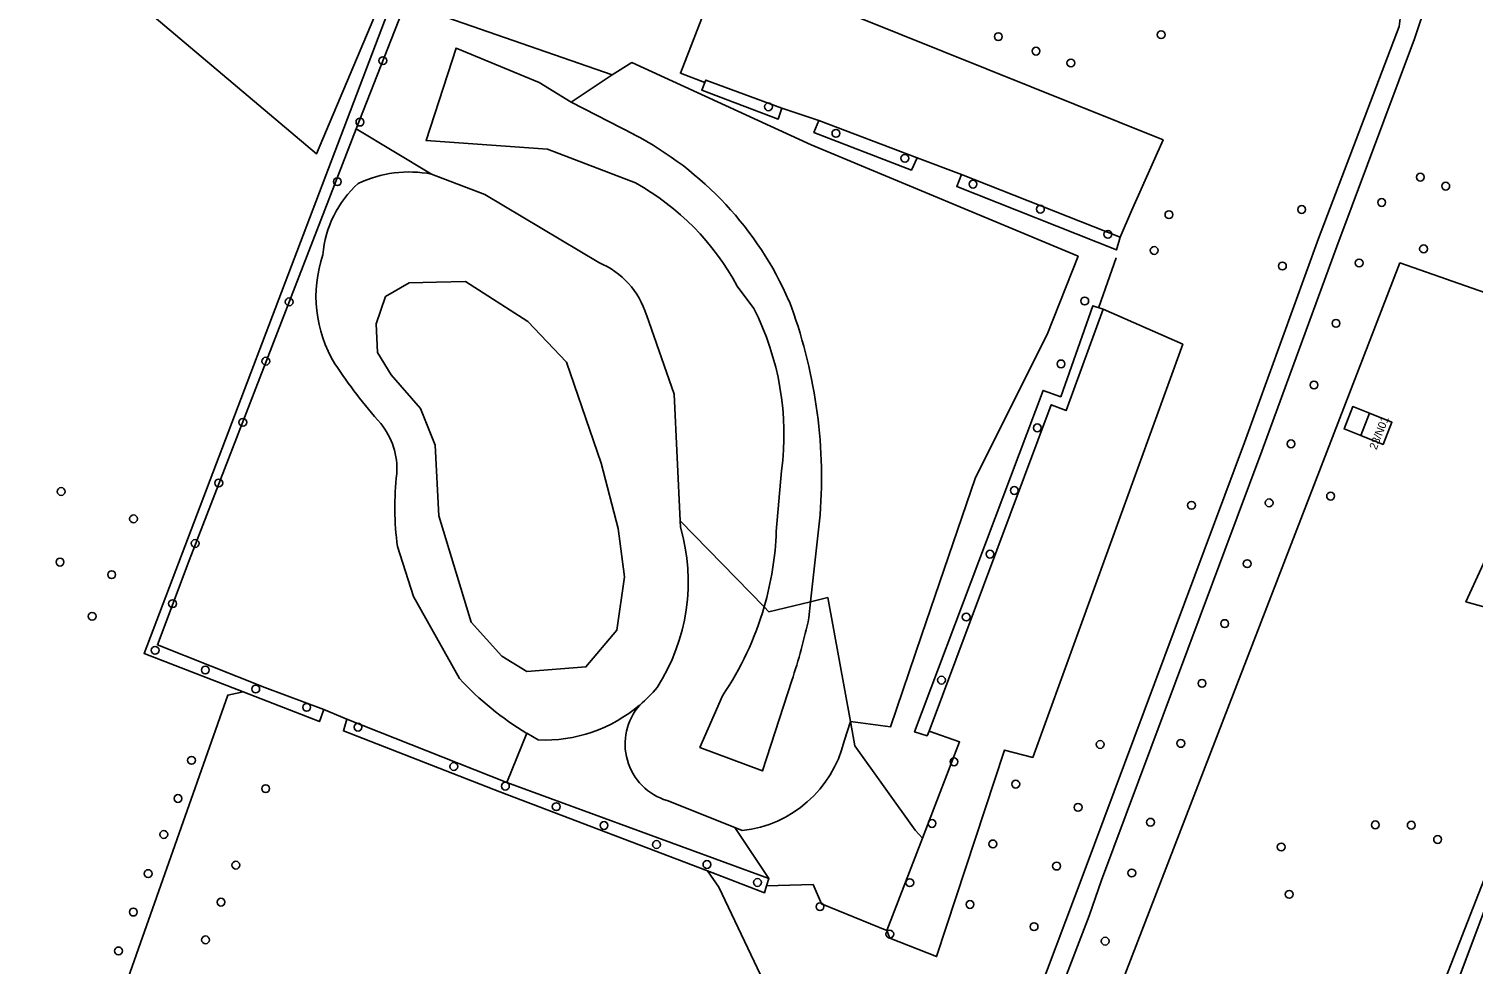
# Model space of a CAD drawing. Extents: x 155209 to 156748, y 385356 to 388487.
# Drawn here: x 155473 to 155653.4, y 386622.5 to 386739.4 of the extents above; entities that cross this region are included whole.
import ezdxf

# ---------------------------------------------------------------- set-up
doc = ezdxf.new("R2010")
doc.units = 0
for name, color, linetype in [('IMGEO_Boom', 7, 'Continuous'), ('IMGEO_Erf', 7, 'Continuous'), ('IMGEO_Gemengd_bos', 7, 'Continuous'), ('IMGEO_Groenvoorziening', 7, 'Continuous'), ('IMGEO_Haag', 7, 'Continuous'), ('IMGEO_Hek', 7, 'Continuous'), ('IMGEO_Loofbos', 7, 'Continuous'), ('IMGEO_Meer_plas_ven_vijver', 7, 'Continuous'), ('IMGEO_Oever', 7, 'Continuous'), ('IMGEO_Pand', 7, 'Continuous'), ('IMGEO_Pand_nummerreeks', 7, 'Continuous'), ('IMGEO_Rijbaan_lokaal_halfverhard', 7, 'Continuous')]:
    doc.layers.add(name, color=color, linetype=linetype)

msp = doc.modelspace()

# ---------------------------------------------------------------- linework, layer by layer
at = {"layer": 'IMGEO_Boom'}
for centre in [(155594.11, 386738.47), (155614.46, 386738.72), (155517.21, 386735.47), (155598.82, 386736.66), (155603.18, 386735.18), (155565.39, 386729.7), (155514.34, 386727.79), (155573.82, 386726.38), (155582.43, 386723.26), (155646.85, 386720.9), (155511.51, 386720.34), (155590.95, 386720.03), (155650.02, 386719.78), (155642.02, 386717.74), (155599.37, 386716.9), (155615.43, 386716.21), (155632.02, 386716.86), (155607.8, 386713.76), (155613.59, 386711.74), (155647.25, 386711.94), (155639.2, 386710.17), (155629.61, 386709.79), (155505.5, 386705.31), (155604.91, 386705.41), (155636.31, 386702.62), (155502.58, 386697.89), (155601.95, 386697.55), (155633.55, 386694.91), (155499.71, 386690.24), (155598.98, 386689.56), (155630.68, 386687.56), (155477.01, 386681.59), (155496.7, 386682.66), (155596.11, 386681.73), (155635.63, 386681.02), (155618.25, 386679.87), (155627.95, 386680.18), (155486.05, 386678.18), (155493.75, 386675.1), (155593.07, 386673.77), (155476.86, 386672.77), (155625.21, 386672.57), (155483.32, 386671.2), (155490.93, 386667.58), (155480.88, 386665.99), (155590.1, 386665.9), (155622.39, 386665.08), (155488.75, 386661.74), (155495.02, 386659.27), (155587.01, 386658.01), (155619.57, 386657.61), (155501.32, 386656.9), (155507.68, 386654.61), (155514.1, 386652.13), (155606.84, 386649.97), (155616.91, 386650.1), (155493.3, 386647.99), (155526.07, 386647.21), (155588.58, 386647.8), (155596.29, 386645.01), (155491.6, 386643.21), (155502.56, 386644.44), (155532.52, 386644.75), (155538.87, 386642.19), (155604.08, 386642.1), (155544.84, 386639.84), (155585.83, 386640.09), (155613.12, 386640.24), (155641.22, 386639.91), (155645.71, 386639.87), (155489.83, 386638.71), (155649, 386638.09), (155551.4, 386637.45), (155593.43, 386637.53), (155629.46, 386637.15), (155498.84, 386634.88), (155557.7, 386634.96), (155601.39, 386634.76), (155487.88, 386633.82), (155564.02, 386632.71), (155583.05, 386632.68), (155610.79, 386633.9), (155630.46, 386631.22), (155486.02, 386629.01), (155496.98, 386630.25), (155571.83, 386629.68), (155590.57, 386629.96), (155598.58, 386627.18), (155495.05, 386625.53), (155580.55, 386626.25), (155607.46, 386625.37), (155484.17, 386624.15)]:
    msp.add_circle(centre, 0.489, dxfattribs=at)
at = {"layer": 'IMGEO_Erf'}
msp.add_lwpolyline([(155640.49, 386691.38), (155638.4, 386692.22), (155637.32, 386689.42), (155639.41, 386688.59)], close=True, dxfattribs=at)
at = {"layer": 'IMGEO_Gemengd_bos'}
for points in [[(155429, 386766.39), (155442.17, 386765.25), (155453.97, 386761.78), (155456.24, 386773.38), (155448.12, 386779.05), (155437.51, 386783.89), (155451.92, 386808.13), (155477.38, 386797.93), (155505.35, 386780.3), (155502.98, 386770.15), (155524.05, 386759.67), (155508.92, 386723.82), (155488.64, 386740.97), (155469.58, 386744.62)], [(155554.38, 386733.89), (155559.71, 386747.69), (155614.71, 386725.57), (155610.76, 386716.71), (155609.34, 386713.39), (155608.88, 386711.8), (155588.92, 386719.73), (155589.49, 386721.25), (155583.96, 386723.33), (155583.26, 386721.79), (155571.06, 386726.49), (155571.68, 386727.98), (155567.07, 386729.53), (155566.62, 386728.16), (155557.06, 386731.77), (155557.42, 386732.74)], [(155557.42, 386732.74), (155557.06, 386731.77), (155566.62, 386728.16), (155567.07, 386729.53), (155557.55, 386733.04)], [(155571.68, 386727.98), (155571.06, 386726.49), (155583.26, 386721.79), (155583.96, 386723.33)], [(155589.49, 386721.25), (155588.92, 386719.73), (155608.88, 386711.8), (155609.34, 386713.39)], [(155607.21, 386704.4), (155605.92, 386704.82), (155601.92, 386693.45), (155599.71, 386694.23), (155583.65, 386651.53), (155585.21, 386651.06), (155585.46, 386651.62), (155600.73, 386692.44), (155602.58, 386691.71)]]:
    msp.add_lwpolyline(points, close=True, dxfattribs=at)
for points in [[(155634.14, 386713.25), (155644.18, 386739.73), (155644.34, 386740.74), (155643.64, 386741.11), (155602.96, 386756.31), (155548.13, 386775.92), (155545.77, 386776.43)], [(155485.14, 386620.07), (155497.83, 386656.14), (155499.74, 386656.54), (155487.37, 386661.36), (155524.86, 386760.1)], [(155520.05, 386742.67), (155545.88, 386733.7), (155548.3, 386735.23), (155570.71, 386724.93), (155604.08, 386711.01), (155600.2, 386701.22), (155591.24, 386683.36), (155584.5, 386663.6), (155580.62, 386652.16), (155575.62, 386652.84), (155576.18, 386649.81), (155583.73, 386639.23), (155584.63, 386638.24), (155589.27, 386650.29), (155585.46, 386651.62), (155585.21, 386651.06), (155583.65, 386651.53), (155599.71, 386694.23), (155601.92, 386693.45), (155605.92, 386704.82), (155607.21, 386704.4), (155617.16, 386700), (155598.42, 386648.34), (155594.89, 386649.26), (155586.4, 386623.44), (155580.55, 386625.76), (155580.19, 386626.71), (155572.02, 386630.03), (155570.97, 386632.44), (155565.14, 386632.28), (155564.88, 386631.43), (155557.77, 386634.17), (155559.17, 386632.13), (155564.4, 386621.18)], [(155600.2, 386701.22), (155604.08, 386711.01), (155570.71, 386724.93), (155548.3, 386735.23), (155545.88, 386733.7), (155540.72, 386730.27), (155548.59, 386726.23)], [(155584.86, 386581.8), (155593.26, 386603.28), (155604.83, 386634.04), (155624.86, 386687.72), (155634.14, 386713.25)], [(155571.83, 386678.68), (155570.65, 386667.82), (155572.79, 386668.33), (155575.62, 386652.84), (155580.62, 386652.16), (155584.5, 386663.6), (155591.24, 386683.36), (155600.2, 386701.22)]]:
    msp.add_lwpolyline(points, dxfattribs=at)
for centre, radius, start, end in [((155528.8, 386688.4), 42.7, 23.5165, 62.3943), ((155509.69, 386683.33), 62.32, 355.7271, 20.7754)]:
    msp.add_arc(centre, radius, start, end, dxfattribs=at)
at = {"layer": 'IMGEO_Groenvoorziening'}
for points in [[(155524.05, 386759.67), (155502.98, 386770.15), (155488.64, 386740.97), (155508.92, 386723.82)], [(155489.03, 386662.42), (155492.99, 386672.97), (155513.88, 386726.96), (155520.05, 386742.67), (155526.72, 386759.39), (155524.86, 386760.1), (155487.37, 386661.36), (155499.74, 386656.54), (155509.27, 386652.83), (155509.85, 386654.32), (155502.46, 386657.1)], [(155559.71, 386747.69), (155554.38, 386733.89), (155557.42, 386732.74), (155557.55, 386733.04), (155567.07, 386729.53), (155571.68, 386727.98), (155583.96, 386723.33), (155589.49, 386721.25), (155609.34, 386713.39), (155610.76, 386716.71), (155614.71, 386725.57)], [(155609.41, 386594.06), (155600.79, 386597.51), (155644.3, 386710.17), (155668.19, 386701.83), (155652.54, 386667.82), (155666.82, 386663.83), (155639.02, 386592.67), (155625.52, 386597.7), (155615.16, 386569.9), (155603.8, 386572.97), (155603.06, 386575.78), (155593.6, 386579.74), (155598.69, 386593.98), (155608.22, 386590.58)], [(155617.16, 386700), (155607.21, 386704.4), (155602.58, 386691.71), (155600.73, 386692.44), (155585.46, 386651.62), (155589.27, 386650.29), (155584.63, 386638.24), (155580.19, 386626.71), (155580.55, 386625.76), (155586.4, 386623.44), (155594.89, 386649.26), (155598.42, 386648.34)], [(155559.17, 386632.13), (155557.77, 386634.17), (155531.83, 386644.04), (155512.27, 386651.66), (155512.7, 386653.15), (155509.85, 386654.32), (155509.27, 386652.83), (155499.74, 386656.54), (155497.83, 386656.14), (155485.14, 386620.07), (155519.77, 386606.37), (155574.54, 386583.62), (155584.21, 386612.25), (155564.4, 386621.18)], [(155532.68, 386645.23), (155512.7, 386653.15), (155512.27, 386651.66), (155531.83, 386644.04), (155557.77, 386634.17), (155564.88, 386631.43), (155565.14, 386632.28), (155565.45, 386633.21)]]:
    msp.add_lwpolyline(points, close=True, dxfattribs=at)
for points in [[(155687.33, 386713.23), (155695.66, 386734.59), (155661.19, 386747.92), (155654.58, 386750.61), (155650.78, 386752.11), (155646.13, 386738.19), (155636.4, 386712.24), (155627.03, 386686.65), (155606.99, 386633), (155605.46, 386628.53), (155594.88, 386600.99), (155587.3, 386580.96)], [(155523.27, 386721.29), (155513.88, 386726.96), (155492.99, 386672.97), (155489.03, 386662.42), (155502.46, 386657.1), (155509.85, 386654.32), (155512.7, 386653.15), (155532.68, 386645.23), (155535.18, 386651.36)], [(155564.85, 386667.17), (155554.36, 386677.91), (155554.4, 386677.12)], [(155526.79, 386658.21), (155521.02, 386668.47), (155519.02, 386674.72)], [(155570.43, 386665.81), (155570.65, 386667.82), (155565.43, 386666.57), (155564.85, 386667.17)], [(155574.84, 386650.36), (155575.62, 386652.84), (155572.79, 386668.33), (155570.65, 386667.82), (155570.43, 386665.81)], [(155559.66, 386656.05), (155556.83, 386649.59), (155564.65, 386646.65), (155568.3, 386657.96)], [(155568.3, 386657.96), (155564.65, 386646.65), (155556.83, 386649.59), (155559.66, 386656.05)], [(155576.18, 386649.81), (155575.62, 386652.84), (155574.84, 386650.36)], [(155536.61, 386650.53), (155535.18, 386651.36), (155532.68, 386645.23), (155565.45, 386633.21), (155561.2, 386639.58), (155552.72, 386642.95)], [(155562.12, 386639.22), (155561.2, 386639.58), (155565.45, 386633.21), (155565.14, 386632.28), (155570.97, 386632.44), (155572.02, 386630.03), (155580.19, 386626.71), (155584.63, 386638.24), (155583.73, 386639.23), (155576.18, 386649.81)], [(155723.96, 386623.91), (155723.78, 386623.66), (155661.74, 386647.58), (155649.36, 386614.6), (155654.71, 386612.58), (155718.88, 386588.39)], [(155649.36, 386614.6), (155661.74, 386647.58)], [(155552.72, 386642.95), (155561.2, 386639.58), (155562.12, 386639.22)]]:
    msp.add_lwpolyline(points, dxfattribs=at)
for centre, radius, start, end in [((155520.48, 386706.9), 14.65, 79.0403, 115.6529), ((155523.05, 386710.15), 13.37, 131.7858, 175.4859), ((155525.02, 386705.97), 16.17, 161.1281, 211.2567), ((155567.03, 386734.46), 66.91, 213.4524, 221.5404), ((155510.03, 386684.44), 8.93, 356.0961, 39.2171), ((155556.42, 386679.63), 37.72, 173.6046, 187.4889), ((155530.83, 386670.33), 24.53, 327.3618, 16.0656), ((155526.9, 386678.13), 39.5, 326.0222, 343.8961), ((155526.9, 386678.13), 39.5, 326.0222, 343.8961), ((155498.28, 386681.19), 73.78, 341.6442, 347.9678), ((155498.28, 386681.19), 73.78, 341.6442, 347.9678), ((155555.47, 386684.79), 39.11, 222.8249, 238.7488), ((155537.49, 386668.8), 18.24, 310.3425, 320.1013), ((155537.4, 386668.87), 18.35, 267.5225, 310.4059), ((155554.85, 386650.02), 7.38, 138.6882, 253.2457), ((155554.85, 386650.02), 7.38, 138.6882, 253.2457), ((155560.57, 386653.82), 14.68, 276.0714, 346.3954), ((155560.57, 386653.82), 14.68, 276.0714, 346.3954)]:
    msp.add_arc(centre, radius, start, end, dxfattribs=at)
at = {"layer": 'IMGEO_Haag'}
for points in [[(155520.05, 386742.67), (155526.72, 386759.39), (155524.86, 386760.1), (155487.37, 386661.36), (155499.74, 386656.54), (155509.27, 386652.83), (155509.85, 386654.32), (155502.46, 386657.1), (155489.03, 386662.42), (155492.99, 386672.97), (155513.88, 386726.96)], [(155557.06, 386731.77), (155566.62, 386728.16), (155567.07, 386729.53), (155557.55, 386733.04), (155557.42, 386732.74)], [(155571.68, 386727.98), (155571.06, 386726.49), (155583.26, 386721.79), (155583.96, 386723.33)], [(155589.49, 386721.25), (155588.92, 386719.73), (155608.88, 386711.8), (155609.34, 386713.39)], [(155607.21, 386704.4), (155605.92, 386704.82), (155601.92, 386693.45), (155599.71, 386694.23), (155583.65, 386651.53), (155585.21, 386651.06), (155585.46, 386651.62), (155600.73, 386692.44), (155602.58, 386691.71)], [(155565.45, 386633.21), (155532.68, 386645.23), (155512.7, 386653.15), (155512.27, 386651.66), (155531.83, 386644.04), (155557.77, 386634.17), (155564.88, 386631.43), (155565.14, 386632.28)]]:
    msp.add_lwpolyline(points, close=True, dxfattribs=at)
at = {"layer": 'IMGEO_Hek'}
for points in [[(155608.83, 386710.8), (155606.67, 386704.64)], [(155639.41, 386688.59), (155637.32, 386689.42), (155638.4, 386692.22), (155640.49, 386691.38)], [(155584.63, 386638.24), (155589.27, 386650.29)], [(155640.23, 386590.29), (155661.74, 386647.58)], [(155580.19, 386626.71), (155584.63, 386638.24)], [(155570.97, 386632.44), (155572.02, 386630.03), (155580.19, 386626.71)]]:
    msp.add_lwpolyline(points, dxfattribs=at)
at = {"layer": 'IMGEO_Loofbos'}
for points in [[(155548.78, 386720.2), (155537.79, 386724.39), (155522.61, 386725.48), (155526.36, 386737.05), (155536.74, 386732.73), (155540.72, 386730.27), (155545.88, 386733.7), (155520.05, 386742.67), (155513.88, 386726.96), (155523.27, 386721.29), (155529.95, 386718.75), (155544.18, 386710.22)], [(155548.59, 386726.23), (155540.72, 386730.27), (155536.74, 386732.73), (155526.36, 386737.05), (155522.61, 386725.48), (155537.79, 386724.39), (155548.78, 386720.2)], [(155561.49, 386707.28), (155563.56, 386704.49)], [(155563.56, 386704.49), (155561.49, 386707.28)], [(155550.15, 386703.67), (155553.62, 386693.77), (155554.36, 386677.91), (155564.85, 386667.17)], [(155567.02, 386684.18), (155566.37, 386676.6)], [(155566.37, 386676.6), (155567.02, 386684.18)], [(155564.85, 386667.17), (155565.43, 386666.57), (155570.65, 386667.82), (155571.83, 386678.68)]]:
    msp.add_lwpolyline(points, dxfattribs=at)
for points in [[(155652.54, 386667.82), (155668.19, 386701.83), (155644.3, 386710.17), (155600.79, 386597.51), (155609.41, 386594.06), (155608.22, 386590.58), (155603.06, 386575.78), (155603.8, 386572.97), (155615.16, 386569.9), (155625.52, 386597.7), (155639.02, 386592.67), (155666.82, 386663.83)], [(155637.32, 386689.42), (155638.4, 386692.22), (155640.49, 386691.38), (155643.29, 386690.26), (155642.19, 386687.48), (155639.41, 386688.59)]]:
    msp.add_lwpolyline(points, close=True, dxfattribs=at)
for centre, radius, start, end in [((155528.8, 386688.4), 42.7, 23.5165, 62.3943), ((155532.6, 386691.57), 32.89, 28.5423, 60.5139), ((155532.6, 386691.57), 32.89, 28.5423, 60.5139), ((155540.24, 386700.63), 10.36, 17.0366, 67.6466), ((155509.69, 386683.33), 62.32, 355.7271, 20.7754), ((155532.42, 386688.74), 34.9, 352.4872, 26.8297), ((155532.42, 386688.74), 34.9, 352.4872, 26.8297), ((155526.99, 386678.1), 39.41, 343.9004, 357.8143), ((155526.99, 386678.1), 39.41, 343.9004, 357.8143)]:
    msp.add_arc(centre, radius, start, end, dxfattribs=at)
at = {"layer": 'IMGEO_Meer_plas_ven_vijver'}
msp.add_lwpolyline([(155523.89, 386707.77), (155520.51, 386707.68), (155517.55, 386705.98), (155516.38, 386702.58), (155516.52, 386698.98), (155518.24, 386696.19), (155521.89, 386691.96), (155523.74, 386687.38), (155524.18, 386678.55), (155528.25, 386665.27), (155532.06, 386661.02), (155535.21, 386659.09), (155542.58, 386659.66), (155546.43, 386664.27), (155547.41, 386670.91), (155546.62, 386676.98), (155544.49, 386685.14), (155540.14, 386697.76), (155535.34, 386702.85), (155527.52, 386707.84)], close=True, dxfattribs=at)
at = {"layer": 'IMGEO_Oever'}
for points in [[(155544.18, 386710.22), (155529.95, 386718.75), (155523.27, 386721.29)], [(155554.4, 386677.12), (155554.36, 386677.91), (155553.62, 386693.77), (155550.15, 386703.67)], [(155519.02, 386674.72), (155521.02, 386668.47), (155526.79, 386658.21)], [(155535.18, 386651.36), (155536.61, 386650.53)]]:
    msp.add_lwpolyline(points, dxfattribs=at)
msp.add_lwpolyline([(155523.89, 386707.77), (155527.52, 386707.84), (155535.34, 386702.85), (155540.14, 386697.76), (155544.49, 386685.14), (155546.62, 386676.98), (155547.41, 386670.91), (155546.43, 386664.27), (155542.58, 386659.66), (155535.21, 386659.09), (155532.06, 386661.02), (155528.25, 386665.27), (155524.18, 386678.55), (155523.74, 386687.38), (155521.89, 386691.96), (155518.24, 386696.19), (155516.52, 386698.98), (155516.38, 386702.58), (155517.55, 386705.98), (155520.51, 386707.68)], close=True, dxfattribs=at)
for centre, radius, start, end in [((155520.48, 386706.9), 14.65, 79.0403, 115.6529), ((155523.05, 386710.15), 13.37, 131.7858, 175.4859), ((155525.02, 386705.97), 16.17, 161.1281, 211.2567), ((155540.24, 386700.63), 10.36, 17.0366, 67.6466), ((155567.03, 386734.46), 66.91, 213.4524, 221.5404), ((155510.03, 386684.44), 8.93, 356.0961, 39.2171), ((155556.42, 386679.63), 37.72, 173.6046, 187.4889), ((155530.83, 386670.33), 24.53, 327.3618, 16.0656), ((155555.47, 386684.79), 39.11, 222.8249, 238.7488), ((155537.49, 386668.8), 18.24, 310.3425, 320.1013), ((155537.4, 386668.87), 18.35, 267.5225, 310.4059)]:
    msp.add_arc(centre, radius, start, end, dxfattribs=at)
at = {"layer": 'IMGEO_Pand'}
msp.add_lwpolyline([(155643.29, 386690.26), (155640.49, 386691.38), (155639.41, 386688.59), (155642.19, 386687.48)], close=True, dxfattribs=at)
at = {"layer": 'IMGEO_Rijbaan_lokaal_halfverhard'}
msp.add_lwpolyline([(155587.3, 386580.96), (155594.88, 386600.99), (155605.46, 386628.53), (155606.99, 386633), (155627.03, 386686.65), (155636.4, 386712.24), (155646.13, 386738.19), (155650.78, 386752.11), (155648.8, 386752.89), (155645.55, 386743.55), (155644.34, 386740.74), (155644.18, 386739.73), (155634.14, 386713.25), (155624.86, 386687.72), (155604.83, 386634.04), (155593.26, 386603.28), (155584.86, 386581.8)], dxfattribs=at)

# ---------------------------------------------------------------- texts
at = {"layer": 'IMGEO_Pand_nummerreeks'}
msp.add_text('23/N01', height=1, rotation=68.5544, dxfattribs=at).set_placement((155641.36, 386686.74))

doc.saveas('drawing.dxf')
